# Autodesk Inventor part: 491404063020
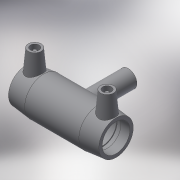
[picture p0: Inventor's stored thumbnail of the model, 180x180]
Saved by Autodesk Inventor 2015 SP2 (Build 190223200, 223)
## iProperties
Created: 2017-06
Part Number: 491404063020
Material: Generic
Description: PLASSON REDUCING TEE 63x20x63
Document SubType Name: Modeling
Designer: KIM
Mass: 57.3761 g
Surface Area: 241.06 cm^2
Volume: 57.3761 cm^3
Density: 1 g/cm^3
Appearance: Default
Author: KIM
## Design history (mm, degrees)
derived "491404.ipt"
feature "Solid1::491404.ipt"
tag "TaggingFeature1"
body "Solid1"
other parameters: "d0" = 167, "d1" = 63, "d2" = 82, "d3" = 49, "d4" = 33.4, "d5" = 73.8, "d6" = 59.85, "d7" = 63, "d8" = 168 deg, "d10" = 19.6, "d11" = 6.53333, "d13" = 167, "d14" = 17.6296, "d17" = 56.7, "d18" = 63, "d19" = 3.52592, "d20" = 168 deg, "d22" = 76.26, "d23" = 82, "d25" = 135 deg, "d26" = 116.9, "d29" = 58, "d30" = 15, "d31" = 66.8, "d34" = 5 deg, "d35" = 15, "d39" = 5 deg, "d41" = 4, "d42" = 14, "d43" = 0, "d45" = 4, "d46" = 6, "d47" = 0, "d48" = -85, "d51" = 0, "d52" = 16, "d54" = 0, "d55" = 73.8, "d56" = 82, "d57" = 58.45, "d58" = 135 deg, "d59" = 49, "d60" = 49, "d61" = 135 deg, "d62" = 85, "d72" = 75.985, "d73" = 37.9925, "d74" = -85, "d75" = 21, "d77" = 0, "d78" = 16, "d80" = 0, "d82" = 44, "d83" = 0, "d84" = 3, "d85" = 0, "d86" = 16.33333, "d87" = 74.7348, "d88" = 6.53333, "d89" = 3, "d90" = 0, "d_" = 63, "L_" = 167, "L_1" = 49, "D_" = 82, "A_" = 58, "d_2" = 12, "H_" = 85
